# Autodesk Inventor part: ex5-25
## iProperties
Created: 2006-03
Part Number: ex5-25
Document SubType Name: Modeling
Designer: Elise Moss
Author: Elise Moss
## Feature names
1. Revolution1
2. Hole1
3. Extrusion1
4. Circular Pattern1
5. Rectangular Pattern1
6. Circular Pattern2
